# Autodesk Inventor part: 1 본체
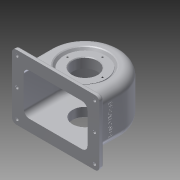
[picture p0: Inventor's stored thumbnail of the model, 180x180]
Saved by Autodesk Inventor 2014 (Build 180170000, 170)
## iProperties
Created: 2015-09
Part Number: 1 본체
Material: 알루미늄 6061
Document SubType Name: Modeling
Designer: aapexcom
Density: 2.71 g/cm^3
Appearance: 알루미늄 - 평지
Mass: 723.862 g
Surface Area: 888.4 cm^2
Volume: 267.108 cm^3
Author: aapexcom
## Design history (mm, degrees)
sketch "스케치1"
  geometry: L1 (63, 52)-(-63, 52); L2 (-70, 45)-(-70, -45); L3 (-63, -52)-(63, -52); L4 (70, -45)-(70, 45); L5 (70, 52)-(-70, -52); L6 (-70, 52)-(70, -52); L7 (68.618, 0)-(-70, 0); L8 (0, -52)-(0, 52); C1 r 2.5 at (62, -44); C2 r 2.5 at (-62, -44); C3 r 2.5 at (62, 44); C4 r 2.5 at (-62, 44); C5 r 2.5 at (-62, 0); C6 r 2.5 at (62, 0); A1 r 7 centre (63, -45) between (63, -52) and (70, -45); A2 r 7 centre (-63, -45) between (-70, -45) and (-63, -52); A3 r 7 centre (-63, 45) between (-63, 52) and (-70, 45); A4 r 7 centre (63, 45) between (70, 45) and (63, 52); 1 further point
  constraints: 16 end point, 10 centre point, 10 point on line, 8 point on circle, 8 tangent, 5 midpoint, 3 equal radius, 2 horizontal, 2 parallel, 1 perpendicular, 1 vertical, 6 other
  dimensions: "d0" = 140 distance of L5.start L6.start; "d1" = 104 distance of L5.end L6.start; "d2" = 5 diameter of C1; "d3" = 8 distance from line of L4 C1.centre; "d4" = 8 distance from line of L3 C1.centre; "d7" = 124 distance of C1.centre C2.centre; "d10" = 88 distance of C1.centre C3.centre; "d13" = 7 radius of A1; "d119" = 5 diameter of C5; "d120" = 5 diameter of C6
extrude "돌출1" new body sketch "스케치1" distance "d14" = 7; taper "d15" = 0 deg
sketch "스케치4"
  geometry: L1 (-70, 0)-(-70, 7) reference; L2 (-70, 7)-(70, 7) reference; L3 (70, 7)-(70, 0) reference; L4 (70, 0)-(-70, 0) reference; L5 (-57, 47)-(-57, 7); L6 (57, 47)-(57, 7); A1 r 57 centre (0, 47) between (57, 47) and (-57, 47); 1 further point
  constraints: 4 end point, 2 perpendicular, 2 point on circle, 2 point on line, 2 tangent, 1 centre point
  dimensions: "d29" = 47 distance of point (0, 0) A1.centre
extrude "돌출2" join sketch "스케치4" stored distance "d31" = 77; taper "d32" = 0 deg
sketch "스케치5"
  geometry: L1 (47, -51.235)-(47, 51.773); L2 (98, -24.5)-(98, 24.5); L3 (89, -33.5)-(67, -33.5); L4 (67, -33.5)-(67, -38.5); L5 (89, 33.5)-(86.747, 33.5); L6 (86.747, 33.5)-(75, 19.5); L7 (75, 19.5)-(67, 19.5); L8 (67, 19.5)-(67, 34.5); L9 (68, 35.5)-(80, 35.5); L10 (80, 35.5)-(80, 34.611); L11 (80.883, 34.29)-(84.416, 38.5); L12 (84.416, 38.5)-(47, 38.5); L13 (67, -38.5)-(47, -38.5); L14 (68, 35.5)-(67, 34.5); L15 (86.747, 33.5)-(67, 33.5); A1 r 9 centre (89, -24.5) between (89, -33.5) and (98, -24.5); A2 r 9 centre (89, 24.5) between (98, 24.5) and (89, 33.5); A3 r 0.5 centre (80.5, 34.611) between (80, 34.611) and (80.883, 34.29); 4 further points
  constraints: 30 end point, 9 point on line, 6 point on circle, 6 tangent, 5 perpendicular, 4 parallel, 3 centre point, 1 equal radius, 1 vertical
  dimensions: "d33" = 47 distance from line of point (0, 0) L1; "d37" = 67 distance of point (98, -33.5) point (98, 33.5); "d38" = 102 diameter of L2 L1; "d41" = 40 diameter of L4 L1; "d42" = 56 diameter of L6.end L1; "d43" = 50 deg angle of L7 L6; "d45" = 40 diameter of L8 L1; "d46" = 66 diameter of L10 L1; "d48" = 5 distance between parallel lines of L6 L11; "d49" = 16 distance of L7.end point (67, 35.5); "d51" = 9 radius of A1; "d52" = 0.5 radius of A3; "d53" = 3 distance between parallel lines of L9 L12; "d54" = 1 distance of L9.start point (67, 35.5); "d55" = 1 distance of L8.end point (67, 35.5) (= d54)
revolve "회전1" stored, may be unused: angle "d56" = 90 deg
chamfer "모따기1" distance "d57" = 1; stored, may be unused: second distance "d58" = 2, angle "d59" = 45 deg
fillet "모깎기1" dims "d60" = 14
sketch "스케치9"
  geometry: L1 (-51, 47)-(-51, 0); L2 (51, 47)-(51, 0); L3 (-51, 0)-(-51, -13.955); L4 (-51, -13.955)-(51, -13.955); L5 (51, -13.955)-(51, 0); A1 r 51 centre (0, 47) between (51, 47) and (-51, 47); 1 further point
  constraints: 10 end point, 3 parallel, 2 point on circle, 2 tangent, 1 centre point, 1 perpendicular, 1 vertical
  dimensions: "d67" = 102 diameter of A1; "d68" = 47 distance of point (0, 0) A1.centre
extrude "돌출3" cut sketch "스케치9" stored distance "d69" = 67; taper "d70" = 0 deg
fillet "모깎기2" dims "d71" = 9
revolve "회전2" stored, may be unused: angle "d72" = 90 deg
sketch "스케치10"
  geometry: C1 r 20 at (0, 47) reference; C2 r 31 at (0, 47); 1 further point
  constraints: 1 centre point, 1 coincident
  dimensions: "d73" = 62 diameter of C2
extrude "돌출4" join sketch "스케치10" distance "d74" = 10; taper "d75" = 0 deg
sketch "스케치11"
  geometry: L1 (-70, 0)-(-70, 7) reference; L2 (-70, 7)-(-57, 7) reference; L3 (-57, 7)-(-57, 47) reference; L4 (57, 47)-(57, 7) reference; L5 (57, 7)-(70, 7) reference; L6 (70, 7)-(70, 0) reference; L7 (70, 0)-(51, 0) reference; L8 (51, 0)-(51, 47) reference; L9 (-51, 47)-(-51, 0) reference; L10 (-51, 0)-(-70, 0) reference; L11 (0, 104)-(0, 110); L12 (0, 110)-(6, 110); L13 (6, 110)-(7.137, 103.551); L14 (6, 110)-(6, 122.205); A1 r 57 centre (0, 47) between (57, 47) and (-57, 47) reference; A2 r 51 centre (0, 47) between (51, 47) and (-51, 47) reference; 1 further point
  constraints: 8 end point, 3 perpendicular, 2 point on circle
  dimensions: "d76" = 6 distance of L11.start L11.end; "d77" = 6 distance of L11.end L12.end; "d78" = 10 deg angle of L14 L13
revolve "회전3" sketch "스케치11" stored, may be unused: angle "d79" = 90 deg
fillet "모깎기3" dims "d80" = 3
sketch "스케치12"
  geometry: C1 r 6 at (0, 0) reference; 1 further point
  constraints: 1 coincident
hole "구멍1" sketch "스케치12" at (0, 0) diameter "d81" = 4.459; stored, may be unused: countersink angle "d85" = 90 deg, drill point angle "d87" = 118 deg; dims "d82" = 12, "d83" = 4, "d84" = 2, "d86" = 12
sketch "스케치13"
  geometry: C1 r 20 at (0, 0) reference; 2 further points
  dimensions: "d88" = 24 distance of point (0, 24) C1.centre
hole "구멍2" sketch "스케치13" at (0, 24) diameter "d89" = 2.459; stored, may be unused: countersink angle "d93" = 90 deg, drill point angle "d95" = 118 deg; dims "d90" = 6, "d91" = 4, "d92" = 2, "d94" = 8
sketch "스케치14"
  geometry: C1 r 33 at (0, 0) reference; 2 further points
  dimensions: "d99" = 28 distance of C1.centre point (0, 28)
hole "구멍3" sketch "스케치14" at (0, 28) diameter "d100" = 2.459; stored, may be unused: countersink angle "d104" = 90 deg, drill point angle "d106" = 118 deg; dims "d101" = 7, "d102" = 4, "d103" = 2, "d105" = 9
fillet "모깎기4" dims "d110" = 3
fillet "모깎기5" dims "d111" = 1
fillet "모깎기6" dims "d112" = 3
chamfer "모따기2" distance "d113" = 1; stored, may be unused: second distance "d114" = 2, angle "d115" = 45 deg
sketch "스케치15"
  geometry: L1 (69.5, -47)-(-20.5, -47) reference; 3 further points
  constraints: 1 midpoint, 1 vertical alignment, 1 other
  dimensions: "d116" = 30 distance from line of L1 point (24.5, -17)
extrude "돌출5" join sketch "스케치15" distance "d117" = 0.5; taper "d118" = 0 deg; dims "d52" = 0.5
sketch "스케치16"
  geometry: C1 r 2.5 at (-62, 0); C2 r 2.5 at (62, 0); 1 further point
  constraints: 2 centre point
  dimensions: "d121" = 5 diameter of C1; "d122" = 5 diameter of C2
extrude "돌출6" cut sketch "스케치16" stored distance "d123" = 0.5; taper "d124" = 0 deg
node "솔리드1"
pattern_circular "원형 패턴1" dims angle "d97" = 360 deg
pattern_circular "원형 패턴2" dims angle "d108" = 360 deg
node "절단 모서리 투영2"
node "절단 모서리 투영5"
other parameters: "d30" = 114
